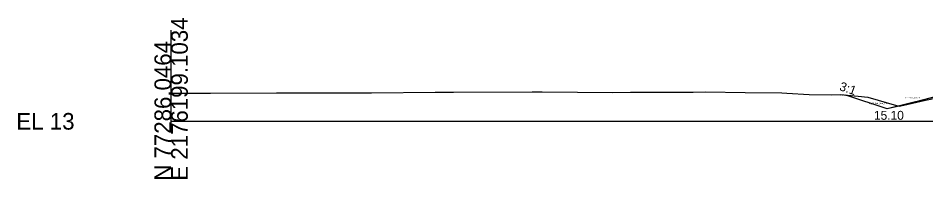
# Model space of a CAD drawing. Extents: x 2177029 to 2201446, y 59897 to 78390.
# Drawn here: x 2199017 to 2199169.5, y 69897.6 to 69924.7 of the extents above; entities that cross this region are included whole.
import ezdxf

# ---------------------------------------------------------------- set-up
doc = ezdxf.new("R2010")
doc.units = 0
for name, color, linetype in [('Exist Cross Section Cell', 7, 'Continuous'), ('Exist PHM Roadway Shape', 7, 'Continuous'), ('Exist XS Ground Line', 7, 'Continuous'), ('Old_Level_3', 7, 'Continuous'), ('Prop CMT Top Wall Envelope', 7, 'Continuous'), ('Prop Hatching', 7, 'Continuous'), ('Prop XS Side Slope Text', 7, 'Continuous')]:
    doc.layers.add(name, color=color, linetype=linetype)

msp = doc.modelspace()

# ---------------------------------------------------------------- linework, layer by layer
at = {"layer": 'Exist Cross Section Cell'}
msp.add_line((2199042.73, 69907.31), (2199242.73, 69907.31), dxfattribs=at)
at = {"layer": 'Exist XS Ground Line'}
msp.add_lwpolyline([(2199042.73, 69912.06), (2199045.57, 69912.06), (2199049.35, 69912.07), (2199060.43, 69912.11), (2199062.86, 69912.09), (2199075.3, 69912.12), (2199076.37, 69912.12), (2199087.06, 69912.21), (2199090.17, 69912.24), (2199103.4, 69912.26), (2199105.03, 69912.25), (2199116.91, 69912.17), (2199119.9, 69912.19), (2199130.42, 69912.24), (2199132.49, 69912.27), (2199139.13, 69912.15), (2199145.28, 69912.09), (2199146.12, 69912.03), (2199149.89, 69911.84), (2199153.58, 69911.77), (2199155.15, 69911.82), (2199158.15, 69911.52), (2199159.77, 69911.36), (2199164.56, 69910), (2199165, 69909.87), (2199165.78, 69910.03), (2199169.46, 69910.87), (2199171.36, 69911.26)], dxfattribs=at)
at = {"layer": 'Old_Level_3'}
msp.add_line((2199042.73, 69905.94), (2199042.73, 69922.68), dxfattribs=at)
at = {"layer": 'Prop Hatching'}
msp.add_line((2199176.72, 69912.84), (2199163.01, 69909.41), dxfattribs=at)
msp.add_lwpolyline([(2199163.01, 69909.41), (2199156.05, 69911.73)], dxfattribs=at)
at = {"layer": 'Prop XS Side Slope Text'}
for points in [[(2199156.05, 69911.73), (2199158.15, 69911.52), (2199159.77, 69911.36), (2199164.56, 69910), (2199165, 69909.87), (2199163.01, 69909.41)], [(2199172.87, 69911.61), (2199171.46, 69911.52), (2199165, 69909.87), (2199165.78, 69910.03), (2199169.46, 69910.87), (2199171.36, 69911.26)]]:
    msp.add_lwpolyline(points, close=True, dxfattribs=at)

# ---------------------------------------------------------------- texts
at = {"layer": 'Exist Cross Section Cell'}
for s, p in [('E 2176199.1034', (2199045.53, 69897.31)), ('N 77286.0464', (2199042.73, 69897.31))]:
    msp.add_text(s, height=2.8, rotation=90, dxfattribs=at).set_placement(p)
msp.add_text('EL 13', height=2.8, dxfattribs=at).set_placement((2199016.73, 69905.91))
at = {"layer": 'Exist PHM Roadway Shape'}
for s, p in [('LT_SS_Hinge_Cut', (2199154.93, 69911.61)), ('LT_Sub_OSS_DLT', (2199166.09, 69911.18)), ('LT_SS_Ditch_Base_Out', (2199159.93, 69910.24))]:
    msp.add_text(s, height=0.2, dxfattribs=at).set_placement(p)
at = {"layer": 'Prop CMT Top Wall Envelope'}
msp.add_text('3:1', height=1.5, rotation=341.5651, dxfattribs=at).set_placement((2199154.87, 69912.58))
for s, height, p in [('15.10', 1.5, (2199160.78, 69907.57)), ('-', 0.0001, (2199042.73, 69907.31)), ('-', 0.0001, (2199042.73, 69907.31))]:
    msp.add_text(s, height=height, dxfattribs=at).set_placement(p)

doc.saveas('drawing.dxf')
